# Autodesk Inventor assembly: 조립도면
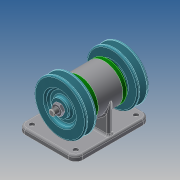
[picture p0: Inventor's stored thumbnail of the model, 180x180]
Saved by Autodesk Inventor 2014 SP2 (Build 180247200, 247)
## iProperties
Created: 2019-09
Part Number: 조립도면
Document SubType Name: Assembly
Designer: kb542-10
Author: kb542-10
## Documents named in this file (10)
- C:\Users\kb542-10\Desktop\490904V1048\조립도면.iam
- C:\Users\kb542-10\Desktop\490904V1048\V-벨트풀리.ipt
- C:\Users\kb542-10\Desktop\490904V1048\너트 M10x1.ipt
- C:\Users\kb542-10\Desktop\490904V1048\베어링 6004.ipt
- C:\Users\kb542-10\Desktop\490904V1048\본체.ipt
- C:\Users\kb542-10\Desktop\490904V1048\볼트 M4.ipt
- C:\Users\kb542-10\Desktop\490904V1048\오일 실 17 30 5.ipt
- C:\Users\kb542-10\Desktop\490904V1048\축.ipt
- C:\Users\kb542-10\Desktop\490904V1048\커버.ipt
- C:\Users\kb542-10\Desktop\490904V1048\키 5 x 5 x 12.ipt
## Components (2 placed, 1 different names)
1. V-벨트풀리:1
2. V-벨트풀리:2
## Named parameters: d15_d14 = 0
